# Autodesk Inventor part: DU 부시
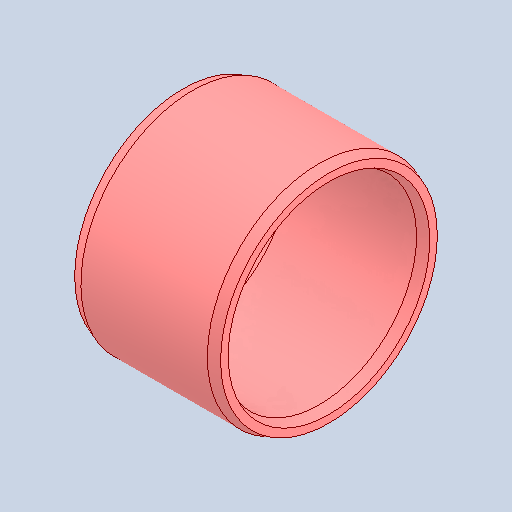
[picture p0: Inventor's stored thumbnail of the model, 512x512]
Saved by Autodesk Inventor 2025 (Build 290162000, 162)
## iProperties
Created: 2026-08
Part Number: DU 부시
Material: 스테인리스스틸
Document SubType Name: Modeling
Designer: KDI
Density: 8 g/cm^3
Appearance: 기본값
Author: jhkim
Sending System: Autodesk Inventor 2027
Preprocessor: ST-DEVELOPER v20.1
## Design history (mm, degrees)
feature "솔리드1"
node "솔리드2"
